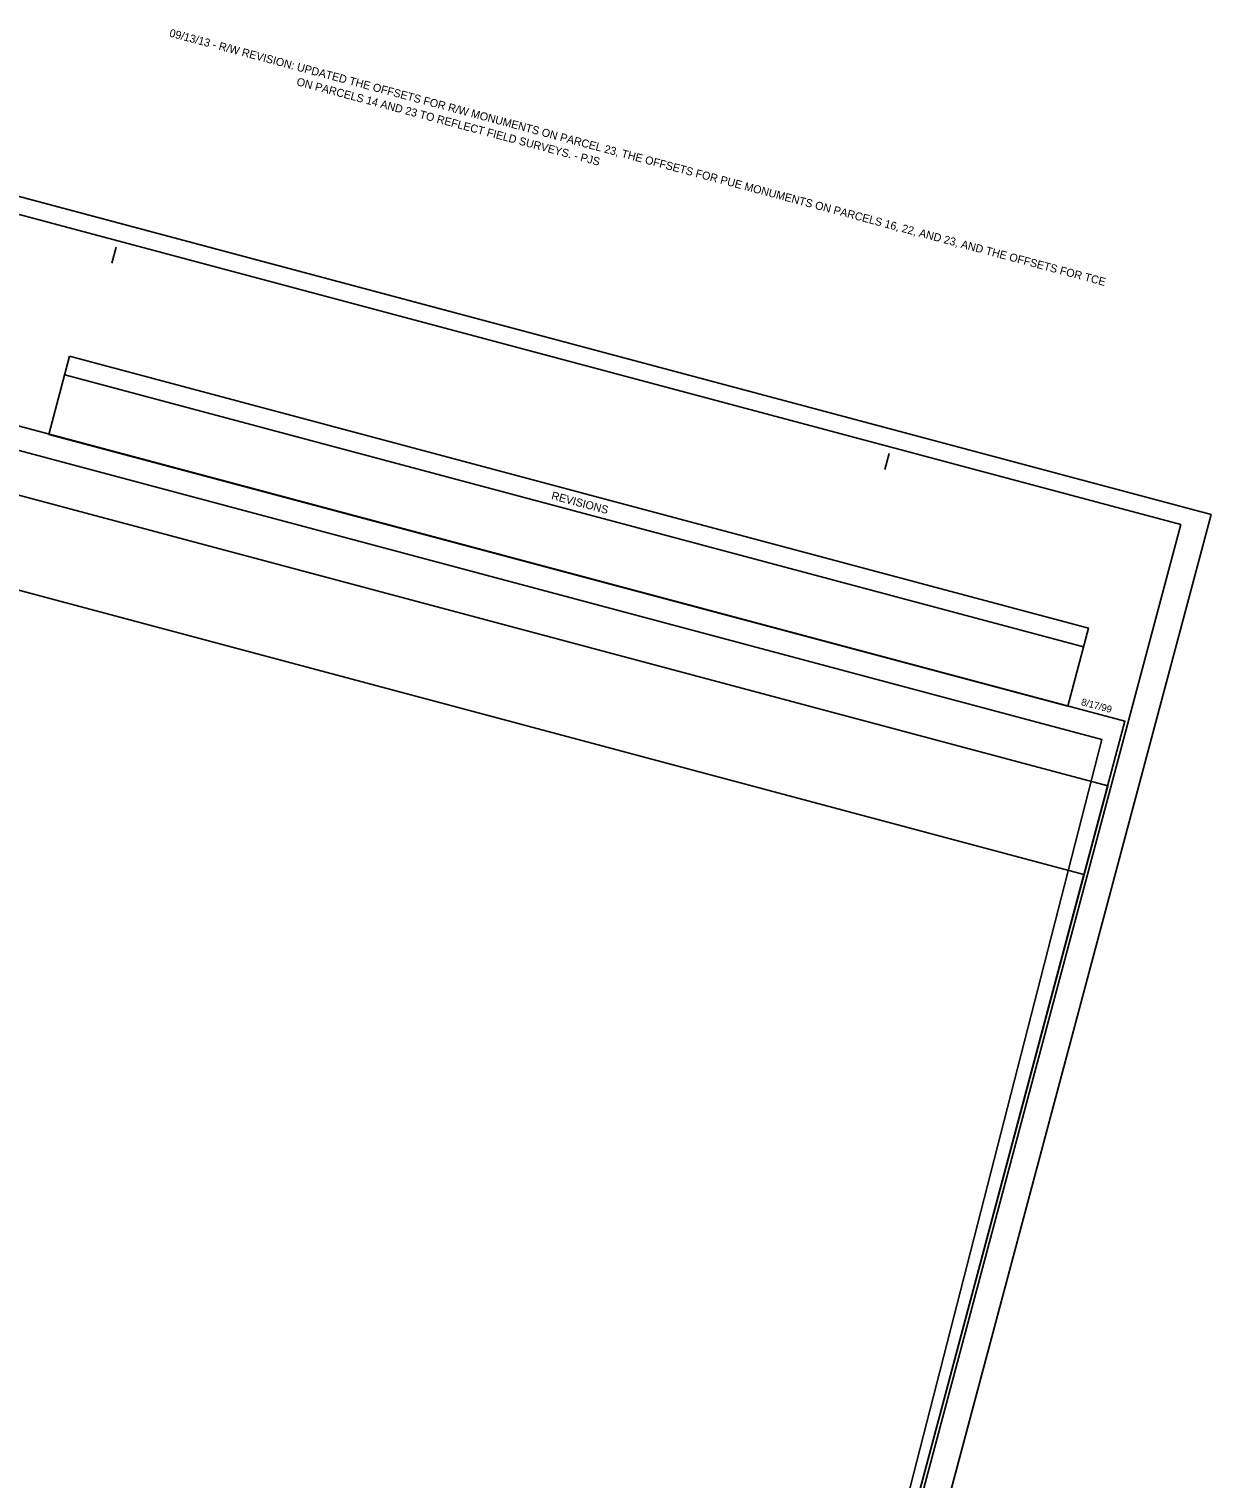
# Model space of a CAD drawing. Extents: x 1782179 to 1783675, y 813964 to 816136.
# Drawn here: x 1782789 to 1783675, y 815050 to 816136 of the extents above; entities that cross this region are included whole.
import ezdxf

# ---------------------------------------------------------------- set-up
doc = ezdxf.new("R2010")
doc.units = 0
for name, color, linetype in [('Sheet Block Revision CELL', 7, 'Continuous'), ('Sheet Clip Boundary CELL', 7, 'Continuous'), ('Sheet Cutting Line CELL', 7, 'Continuous'), ('Sheet Layout Plan Border', 7, 'Continuous'), ('Sheet Plan CELL', 7, 'Continuous'), ('Sheet Plan Layout CELL', 7, 'Continuous'), ('Sheet Plot Border Inside CELL', 7, 'Continuous'), ('Sheet Plot Border Outside CELL', 7, 'Continuous')]:
    doc.layers.add(name, color=color, linetype=linetype)

msp = doc.modelspace()

# ---------------------------------------------------------------- linework, layer by layer
at = {"layer": 'Sheet Block Revision CELL'}
msp.add_line((1782815.8, 815876.7), (1783579.7, 815672.9), dxfattribs=at)
msp.add_lwpolyline([(1782819.5, 815890.7), (1783583.5, 815687), (1783567.9, 815628.5), (1782804, 815832.2)], close=True, dxfattribs=at)
at = {"layer": 'Sheet Clip Boundary CELL'}
msp.add_lwpolyline([(1782607.1, 815866.5), (1782558.9, 815688.6), (1782520.3, 815177.9), (1782448.8, 814938.8), (1782554.3, 814867.2), (1782519.6, 814798.9), (1782507.5, 814733.2), (1783124.8, 814377.4), (1783147.7, 814463.1), (1783193.9, 814449.4), (1783239.4, 814501.8), (1783298.4, 814452.3), (1783593.6, 815603.4)], close=True, dxfattribs=at)
at = {"layer": 'Sheet Cutting Line CELL'}
for p, q in [((1783675.4, 815772.2), (1782617.4, 816054.3)), ((1783241.6, 814145.5), (1783675.4, 815772.2))]:
    msp.add_line(p, q, dxfattribs=at)
at = {"layer": 'Sheet Layout Plan Border'}
for points in [[(1782596.2, 815887.7), (1782209.7, 814438.3), (1783019.9, 814222.2), (1783071.4, 814415.5), (1783275.8, 814361), (1783610.8, 815617.1)], [(1782583.3, 815839.3), (1782222.6, 814486.6), (1783032.8, 814270.5), (1783081.5, 814453.4), (1783285.9, 814398.9), (1783597.9, 815568.8)]]:
    msp.add_lwpolyline(points, close=True, dxfattribs=at)
at = {"layer": 'Sheet Plan CELL'}
for p, q in [((1782854.3, 815972.5), (1782851.1, 815960.4)), ((1783434, 815817.9), (1783430.8, 815805.8)), ((1783610.8, 815617.1), (1783610.8, 815617.1))]:
    msp.add_line(p, q, dxfattribs=at)
for points in [[(1783224.2, 814167.7), (1783610.8, 815617.1), (1782596.2, 815887.7), (1782209.7, 814438.3)], [(1782596.2, 815887.7), (1783610.7, 815617.1), (1783275.8, 814361), (1783130.8, 814399.7), (1783079.2, 814206.4), (1782209.7, 814438.3)]]:
    msp.add_lwpolyline(points, close=True, dxfattribs=at)
at = {"layer": 'Sheet Plan Layout CELL'}
for points in [[(1783610.7, 815617.1), (1782596.2, 815887.7), (1782209.7, 814438.3), (1783019.9, 814222.2), (1783081.5, 814453.4), (1783285.9, 814398.9)], [(1783580.1, 815502.2), (1782565.6, 815772.8), (1782179.1, 814323.4), (1782989.2, 814107.4), (1783050.9, 814338.5), (1783255.2, 814284)]]:
    msp.add_lwpolyline(points, close=True, dxfattribs=at)
at = {"layer": 'Sheet Plot Border Inside CELL'}
msp.add_lwpolyline([(1782633.3, 816036.6), (1782204.1, 814426.9), (1783223.4, 814155), (1783652.7, 815764.7)], close=True, dxfattribs=at)
at = {"layer": 'Sheet Plot Border Outside CELL'}
msp.add_lwpolyline([(1782617.4, 816054.3), (1782183.6, 814427.7), (1783241.6, 814145.5), (1783675.4, 815772.2)], close=True, dxfattribs=at)

# ---------------------------------------------------------------- texts
at = {"layer": 'Sheet Block Revision CELL'}
for s, p in [('09/13/13 - R/W REVISION: UPDATED THE OFFSETS FOR R/W MONUMENTS ON PARCEL 23, THE OFFSETS FOR PUE MONUMENTS ON PARCELS 16, 22, AND 23, AND THE OFFSETS FOR TCE ', (1782893.8, 816130.5)), ('ON PARCELS 14 AND 23 TO REFLECT FIELD SURVEYS. - PJS', (1782989.2, 816094)), ('REVISIONS', (1783180.3, 815783.7))]:
    msp.add_text(s, height=6, rotation=345.0673, dxfattribs=at).set_placement(p)
at = {"layer": 'Sheet Plan CELL'}
msp.add_text('8/17/99', height=5.25, rotation=345.0673, dxfattribs=at).set_placement((1783577.6, 815629.3))

doc.saveas('drawing.dxf')
